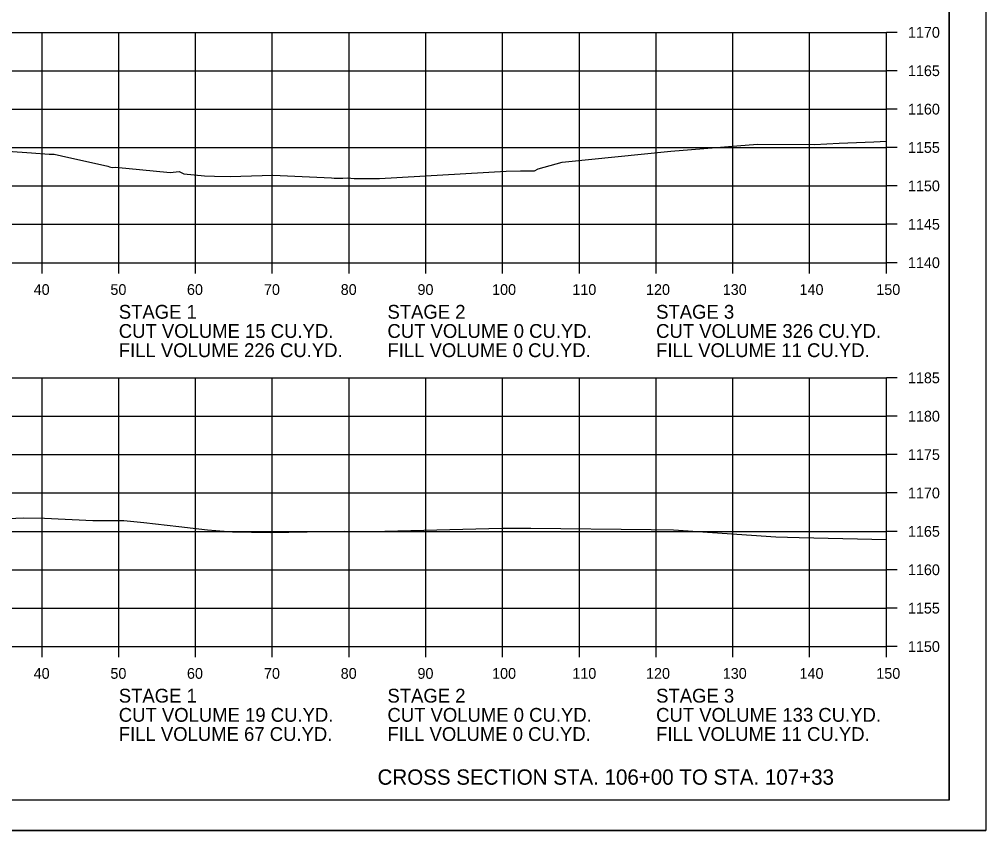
# Model space of a CAD drawing. Extents: x 1368971 to 1374497, y 378717 to 381839.
# Drawn here: x 1371089.8 to 1371215.6, y 378930.4 to 379036.1 of the extents above; entities that cross this region are included whole.
import ezdxf

# ---------------------------------------------------------------- set-up
doc = ezdxf.new("R2010")
doc.units = 0
for name, color, linetype in [('R_Axis', 7, 'Continuous'), ('R_Axis Annot', 7, 'Continuous'), ('R_Border', 7, 'Continuous'), ('R_Draft', 7, 'Continuous'), ('R_Exist Surface', 7, 'Continuous'), ('R_Grid', 7, 'Continuous'), ('R_No Plot', 7, 'Continuous')]:
    doc.layers.add(name, color=color, linetype=linetype)

msp = doc.modelspace()

# ---------------------------------------------------------------- linework, layer by layer
at = {"layer": 'R_Axis'}
for p, q in [((1371202.71, 379004.4), (1371202.71, 379034.4)), ((1371204.11, 379034.4), (1371202.71, 379034.4)), ((1371204.11, 379029.4), (1371202.71, 379029.4)), ((1371204.11, 379024.4), (1371202.71, 379024.4)), ((1371204.11, 379019.4), (1371202.71, 379019.4)), ((1371204.11, 379014.4), (1371202.71, 379014.4)), ((1371204.11, 379009.4), (1371202.71, 379009.4)), ((1370902.71, 379004.4), (1371202.71, 379004.4)), ((1371092.71, 379003), (1371092.71, 379004.4)), ((1371102.71, 379003), (1371102.71, 379004.4)), ((1371112.71, 379003), (1371112.71, 379004.4)), ((1371122.71, 379003), (1371122.71, 379004.4)), ((1371132.71, 379003), (1371132.71, 379004.4)), ((1371142.71, 379003), (1371142.71, 379004.4)), ((1371152.71, 379003), (1371152.71, 379004.4)), ((1371162.71, 379003), (1371162.71, 379004.4)), ((1371172.71, 379003), (1371172.71, 379004.4)), ((1371182.71, 379003), (1371182.71, 379004.4)), ((1371192.71, 379003), (1371192.71, 379004.4)), ((1371202.71, 379003), (1371202.71, 379004.4)), ((1371204.11, 379004.4), (1371202.71, 379004.4)), ((1371202.71, 378954.4), (1371202.71, 378989.4)), ((1371204.11, 378989.4), (1371202.71, 378989.4)), ((1371204.11, 378984.4), (1371202.71, 378984.4)), ((1371204.11, 378979.4), (1371202.71, 378979.4)), ((1371204.11, 378974.4), (1371202.71, 378974.4)), ((1371204.11, 378969.4), (1371202.71, 378969.4)), ((1371204.11, 378964.4), (1371202.71, 378964.4)), ((1371204.11, 378959.4), (1371202.71, 378959.4)), ((1370902.71, 378954.4), (1371202.71, 378954.4)), ((1371092.71, 378953), (1371092.71, 378954.4)), ((1371102.71, 378953), (1371102.71, 378954.4)), ((1371112.71, 378953), (1371112.71, 378954.4)), ((1371122.71, 378953), (1371122.71, 378954.4)), ((1371132.71, 378953), (1371132.71, 378954.4)), ((1371142.71, 378953), (1371142.71, 378954.4)), ((1371152.71, 378953), (1371152.71, 378954.4)), ((1371162.71, 378953), (1371162.71, 378954.4)), ((1371172.71, 378953), (1371172.71, 378954.4)), ((1371182.71, 378953), (1371182.71, 378954.4)), ((1371192.71, 378953), (1371192.71, 378954.4)), ((1371202.71, 378953), (1371202.71, 378954.4)), ((1371204.11, 378954.4), (1371202.71, 378954.4))]:
    msp.add_line(p, q, dxfattribs=at)
at = {"layer": 'R_Border'}
for q in [(1371210.89, 379139.86), (1370894.71, 378934.4)]:
    msp.add_line((1371210.89, 378934.4), q, dxfattribs=at)
at = {"layer": 'R_Exist Surface'}
for points in [[(1371085.13, 379019.14), (1371091.32, 379018.7), (1371093.63, 379018.52), (1371094.31, 379018.52), (1371095.23, 379018.33), (1371101.28, 379016.97), (1371101.52, 379016.9), (1371101.83, 379016.79), (1371102.22, 379016.84), (1371103.61, 379016.69), (1371109.4, 379016.13), (1371110.57, 379016.29), (1371111.17, 379015.96), (1371111.18, 379015.96), (1371113.89, 379015.7), (1371115.17, 379015.65), (1371117.22, 379015.63), (1371122.77, 379015.78), (1371130.42, 379015.43), (1371130.75, 379015.39), (1371131.37, 379015.4), (1371131.9, 379015.39), (1371132.49, 379015.44), (1371133.39, 379015.38), (1371136.19, 379015.35), (1371136.66, 379015.37), (1371153.18, 379016.32), (1371155.04, 379016.37), (1371156.87, 379016.36), (1371157.36, 379016.63), (1371160.46, 379017.49), (1371174.63, 379018.93), (1371185.92, 379019.83), (1371193.33, 379019.78), (1371196.54, 379019.97), (1371201.09, 379020.12), (1371202.71, 379020.24)], [(1371088.31, 378971.06), (1371090.3, 378971.15), (1371093.04, 378971.13), (1371099.34, 378970.81), (1371103.37, 378970.8), (1371105.99, 378970.54), (1371110.54, 378970.03), (1371114.27, 378969.62), (1371117.52, 378969.33), (1371119.98, 378969.28), (1371122.45, 378969.27), (1371132.1, 378969.42), (1371135.66, 378969.39), (1371152.63, 378969.8), (1371156.38, 378969.83), (1371172.06, 378969.65), (1371174.99, 378969.6), (1371188.31, 378968.69), (1371191.36, 378968.6), (1371202.71, 378968.34)]]:
    msp.add_lwpolyline(points, dxfattribs=at)
at = {"layer": 'R_Grid'}
for p, q in [((1370902.71, 379034.4), (1371202.71, 379034.4)), ((1371092.71, 379004.4), (1371092.71, 379034.4)), ((1371102.71, 379004.4), (1371102.71, 379034.4)), ((1371112.71, 379004.4), (1371112.71, 379034.4)), ((1371122.71, 379004.4), (1371122.71, 379034.4)), ((1371132.71, 379004.4), (1371132.71, 379034.4)), ((1371142.71, 379004.4), (1371142.71, 379034.4)), ((1371152.71, 379004.4), (1371152.71, 379034.4)), ((1371162.71, 379004.4), (1371162.71, 379034.4)), ((1371172.71, 379004.4), (1371172.71, 379034.4)), ((1371182.71, 379004.4), (1371182.71, 379034.4)), ((1371192.71, 379004.4), (1371192.71, 379034.4)), ((1371202.71, 379004.4), (1371202.71, 379034.4)), ((1370902.71, 379029.4), (1371202.71, 379029.4)), ((1370902.71, 379024.4), (1371202.71, 379024.4)), ((1370902.71, 379019.4), (1371202.71, 379019.4)), ((1370902.71, 379014.4), (1371202.71, 379014.4)), ((1370902.71, 379009.4), (1371202.71, 379009.4)), ((1370902.71, 379004.4), (1371202.71, 379004.4)), ((1370902.71, 378989.4), (1371202.71, 378989.4)), ((1371092.71, 378954.4), (1371092.71, 378989.4)), ((1371102.71, 378954.4), (1371102.71, 378989.4)), ((1371112.71, 378954.4), (1371112.71, 378989.4)), ((1371122.71, 378954.4), (1371122.71, 378989.4)), ((1371132.71, 378954.4), (1371132.71, 378989.4)), ((1371142.71, 378954.4), (1371142.71, 378989.4)), ((1371152.71, 378954.4), (1371152.71, 378989.4)), ((1371162.71, 378954.4), (1371162.71, 378989.4)), ((1371172.71, 378954.4), (1371172.71, 378989.4)), ((1371182.71, 378954.4), (1371182.71, 378989.4)), ((1371192.71, 378954.4), (1371192.71, 378989.4)), ((1371202.71, 378954.4), (1371202.71, 378989.4)), ((1370902.71, 378984.4), (1371202.71, 378984.4)), ((1370902.71, 378979.4), (1371202.71, 378979.4)), ((1370902.71, 378974.4), (1371202.71, 378974.4)), ((1370902.71, 378969.4), (1371202.71, 378969.4)), ((1370902.71, 378964.4), (1371202.71, 378964.4)), ((1370902.71, 378959.4), (1371202.71, 378959.4)), ((1370902.71, 378954.4), (1371202.71, 378954.4))]:
    msp.add_line(p, q, dxfattribs=at)
at = {"layer": 'R_No Plot'}
msp.add_line((1370882.31, 378930.42), (1371215.64, 378930.42), dxfattribs=at)
for points in [[(1370882.3, 379143.75), (1371215.64, 379143.75), (1371215.64, 378930.42), (1370882.3, 378930.42)], [(1371128.63, 379139.86), (1371128.63, 379129.98), (1371164.36, 379129.98), (1371164.36, 379127.06), (1371187.56, 379127.06), (1371187.56, 379102.73), (1371210.89, 379102.73), (1371210.89, 378934.4), (1370894.71, 378934.4), (1370894.71, 379139.86)]]:
    msp.add_lwpolyline(points, close=True, dxfattribs=at)

# ---------------------------------------------------------------- texts
at = {"layer": 'R_Axis Annot'}
for s, height, p in [('1170', 1.4, (1371205.51, 379033.7)), ('1165', 1.4, (1371205.51, 379028.7)), ('1160', 1.4, (1371205.51, 379023.7)), ('1155', 1.4, (1371205.51, 379018.7)), ('1150', 1.4, (1371205.51, 379013.7)), ('1145', 1.4, (1371205.51, 379008.7)), ('1140', 1.4, (1371205.51, 379003.7)), ('40', 1.4, (1371091.62, 379000.2)), ('50', 1.4, (1371101.62, 379000.2)), ('60', 1.4, (1371111.59, 379000.2)), ('70', 1.4, (1371121.62, 379000.2)), ('80', 1.4, (1371131.62, 379000.2)), ('90', 1.4, (1371141.62, 379000.2)), ('100', 1.4, (1371151.34, 379000.2)), ('110', 1.4, (1371161.79, 379000.2)), ('120', 1.4, (1371171.39, 379000.2)), ('130', 1.4, (1371181.39, 379000.2)), ('140', 1.4, (1371191.39, 379000.2)), ('150', 1.4, (1371201.39, 379000.2)), ('STAGE 1', 1.8, (1371102.71, 378997.1)), ('STAGE 2', 1.8, (1371137.71, 378997.1)), ('STAGE 3', 1.8, (1371172.71, 378997.1)), ('CUT VOLUME 15 CU.YD.', 1.8, (1371102.71, 378994.6)), ('CUT VOLUME 0 CU.YD.', 1.8, (1371137.71, 378994.6)), ('CUT VOLUME 326 CU.YD.', 1.8, (1371172.71, 378994.6)), ('FILL VOLUME 226 CU.YD.', 1.8, (1371102.71, 378992.1)), ('FILL VOLUME 0 CU.YD.', 1.8, (1371137.71, 378992.1)), ('FILL VOLUME 11 CU.YD.', 1.8, (1371172.71, 378992.1)), ('1185', 1.4, (1371205.51, 378988.7)), ('1180', 1.4, (1371205.51, 378983.7)), ('1175', 1.4, (1371205.51, 378978.7)), ('1170', 1.4, (1371205.51, 378973.7)), ('1165', 1.4, (1371205.51, 378968.7)), ('1160', 1.4, (1371205.51, 378963.7)), ('1155', 1.4, (1371205.51, 378958.7)), ('1150', 1.4, (1371205.51, 378953.7)), ('40', 1.4, (1371091.62, 378950.2)), ('50', 1.4, (1371101.62, 378950.2)), ('60', 1.4, (1371111.59, 378950.2)), ('70', 1.4, (1371121.62, 378950.2)), ('80', 1.4, (1371131.62, 378950.2)), ('90', 1.4, (1371141.62, 378950.2)), ('100', 1.4, (1371151.34, 378950.2)), ('110', 1.4, (1371161.79, 378950.2)), ('120', 1.4, (1371171.39, 378950.2)), ('130', 1.4, (1371181.39, 378950.2)), ('140', 1.4, (1371191.39, 378950.2)), ('150', 1.4, (1371201.39, 378950.2)), ('STAGE 1', 1.8, (1371102.71, 378947.1)), ('STAGE 2', 1.8, (1371137.71, 378947.1)), ('STAGE 3', 1.8, (1371172.71, 378947.1)), ('CUT VOLUME 19 CU.YD.', 1.8, (1371102.71, 378944.6)), ('CUT VOLUME 0 CU.YD.', 1.8, (1371137.71, 378944.6)), ('CUT VOLUME 133 CU.YD.', 1.8, (1371172.71, 378944.6)), ('FILL VOLUME 67 CU.YD.', 1.8, (1371102.71, 378942.1)), ('FILL VOLUME 0 CU.YD.', 1.8, (1371137.71, 378942.1)), ('FILL VOLUME 11 CU.YD.', 1.8, (1371172.71, 378942.1))]:
    msp.add_text(s, height=height, dxfattribs=at).set_placement(p)
at = {"layer": 'R_Draft'}
msp.add_text('CROSS SECTION STA. 106+00 TO STA. 107+33', height=2, dxfattribs=at).set_placement((1371136.42, 378936.4))

doc.saveas('drawing.dxf')
